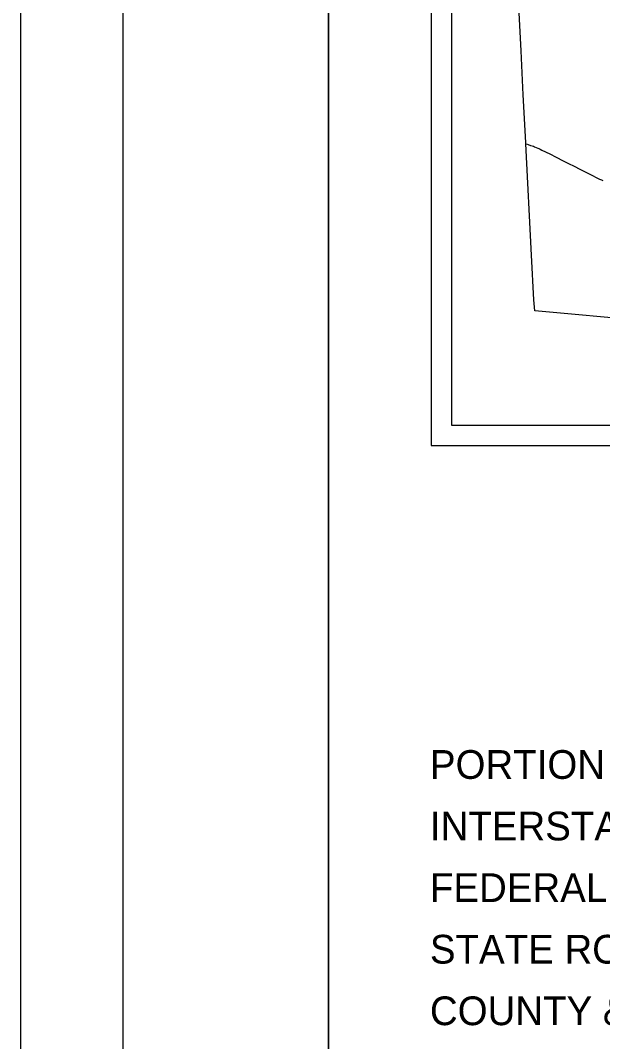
# Model space of a CAD drawing. Extents: x 0 to 34, y 0 to 22.
# Drawn here: x 0 to 2.835, y 11.097 to 16.072 of the extents above; entities that cross this region are included whole.
import ezdxf

# ---------------------------------------------------------------- set-up
doc = ezdxf.new("R2010")
doc.units = 0
for name, color, linetype in [('GM_X_County', 7, 'Continuous'), ('GM_X_State_Route', 7, 'Continuous'), ('SH_Border', 7, 'Continuous'), ('SH_Cut_Line', 7, 'Continuous'), ('SH_Data', 7, 'Continuous'), ('SH_Text', 7, 'Continuous')]:
    doc.layers.add(name, color=color, linetype=linetype)

msp = doc.modelspace()

# ---------------------------------------------------------------- linework, layer by layer
at = {"layer": 'GM_X_County'}
msp.add_lwpolyline([(3.0396, 14.6088), (2.5046, 14.6566), (2.5, 14.7104), (2.4889, 14.9285), (2.4622, 15.4705), (2.4618, 15.4775), (2.4492, 15.71), (2.4386, 15.9232), (2.4341, 16.0159), (2.4234, 16.2017)], dxfattribs=at)
at = {"layer": 'GM_X_State_Route'}
msp.add_lwpolyline([(2.464, 15.4701), (2.4735, 15.4669), (2.4842, 15.4632), (2.4922, 15.4606), (2.4981, 15.4587), (2.5043, 15.4564), (2.5122, 15.453), (2.5193, 15.45), (2.5248, 15.4476), (2.5317, 15.4443), (2.5397, 15.4403), (2.5781, 15.4212), (2.6092, 15.406), (2.6439, 15.3884), (2.6698, 15.3755), (2.6968, 15.3615), (2.7251, 15.3469), (2.7567, 15.3305), (2.7694, 15.3238), (2.8209, 15.2987), (2.8253, 15.2968), (2.8298, 15.2949), (2.8337, 15.2932), (2.8364, 15.2921)], dxfattribs=at)
at = {"layer": 'SH_Border'}
for points in [[(0.5, 21.5), (1.5, 21.5), (1.5, 0.5), (0.5, 0.5)], [(1.5, 21.5), (33.5, 21.5), (33.5, 0.5), (1.5, 0.5)]]:
    msp.add_lwpolyline(points, close=True, dxfattribs=at)
at = {"layer": 'SH_Cut_Line'}
msp.add_lwpolyline([(0, 0), (34, 0), (34, 22), (0, 22)], close=True, dxfattribs=at)
at = {"layer": 'SH_Data'}
for p, q in [((2, 21), (2, 14)), ((2.1, 20.9), (2.1, 14.1)), ((2.1, 14.1), (8.9, 14.1)), ((2.1, 14.1), (2.1, 14.1)), ((2, 14), (9, 14))]:
    msp.add_line(p, q, dxfattribs=at)

# ---------------------------------------------------------------- texts
at = {"layer": 'SH_Text'}
for s, p in [('PORTION TO BE IMPROVED', (1.9944, 12.3767)), ('INTERSTATE HIGHWAY', (1.9944, 12.0767)), ('FEDERAL ROUTES', (1.9944, 11.7767)), ('STATE ROUTES', (1.9944, 11.4767)), ('COUNTY & TOWNSHIP ROADS', (1.9944, 11.1767))]:
    msp.add_text(s, height=0.14, dxfattribs=at).set_placement(p)

doc.saveas('drawing.dxf')
